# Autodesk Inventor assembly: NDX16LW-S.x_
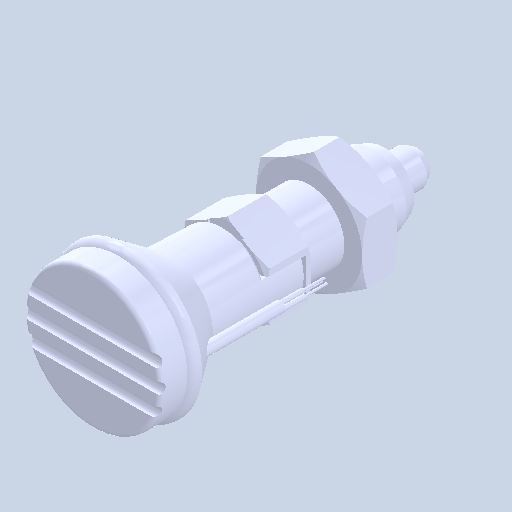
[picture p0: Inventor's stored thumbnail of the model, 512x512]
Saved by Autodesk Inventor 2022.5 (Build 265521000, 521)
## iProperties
Created: 2024-05
Part Number: NDX16LW-S.x_
Document SubType Name: Assembly
Designer: ImaoCorp
Author: ImaoCorp
Sending System: SOLIDWORKS 2022-2022290
MC: AMD64
MC_MODEL: Intel64 Family 6 Model 60 Stepping 3, GenuineIntel
OS: Windows_NT
FRU: Parasolid Version 33.1, build 260,  4-25-2022
FORMAT: text
GUISE: transmit
KEY: FILENDX16LW-S.x_t
DATE: Tue May 21 08:47:47 2024
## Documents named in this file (3)
- X:\14_SW2022-Inv2022\保留中\kipp\KME_データ\n\ndx16lw-s\NDX16LW-S.x_.iam
- X:\14_SW2022-Inv2022\保留中\kipp\KME_データ\n\ndx16lw-s\NDX16LW-S_01.ipt
- X:\14_SW2022-Inv2022\保留中\kipp\KME_データ\n\ndx16lw-s\NDX16LW-S_02.ipt
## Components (2 placed, 2 different names)
1. NDX16LW-S_01
2. NDX16LW-S_02
